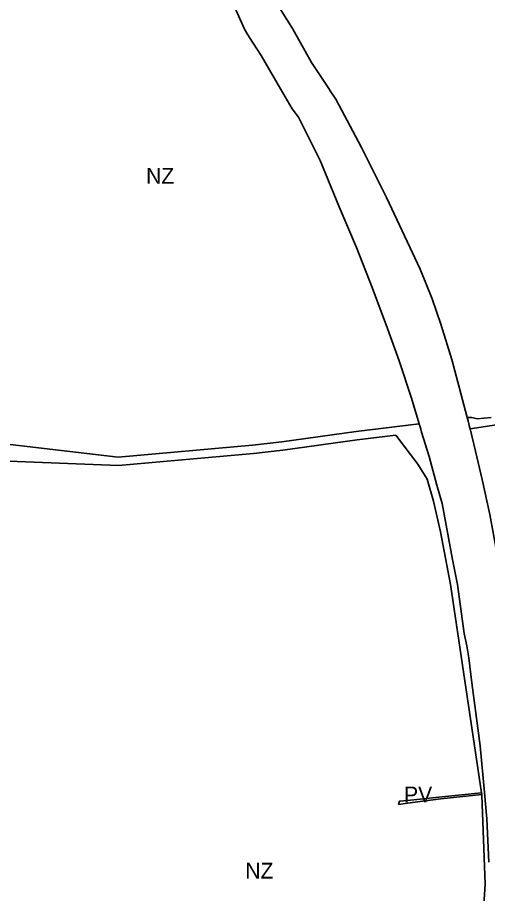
# Model space of a CAD drawing. Extents: x -650451 to -642268, y -1075216 to -1066610.
# Drawn here: x -645447 to -644999, y -1070421 to -1069586 of the extents above; entities that cross this region are included whole.
import ezdxf

# ---------------------------------------------------------------- set-up
doc = ezdxf.new("R2010")
doc.units = 0
doc.header["$LTSCALE"] = 6
doc.layers.add('1', color=7, linetype='Continuous', lineweight=35)
doc.layers.add('2', color=7, linetype='Continuous')

msp = doc.modelspace()

# ---------------------------------------------------------------- linework, layer by layer
at = {"layer": '1'}
msp.add_line((-645004.791, -1070324.889), (-645004.523, -1070326.697), dxfattribs=at)
for points in [[(-645064.052, -1069973.429), (-645071.53, -1069948.89), (-645083.31, -1069913.37), (-645094.42, -1069882.65), (-645108.74, -1069843.58), (-645123.84, -1069805.38), (-645140.27, -1069766.68), (-645153.44, -1069734.71), (-645158.43, -1069722.61), (-645179.12, -1069681.3), (-645185.17, -1069673.38), (-645198.41, -1069650.49), (-645214.76, -1069622.37), (-645225.7, -1069605.32), (-645227.27, -1069602.68), (-645230.42, -1069597.39), (-645242.75, -1069570.26)], [(-645018.28, -1069967.49), (-645024.45, -1069944.43), (-645032.85, -1069912.07), (-645043.5, -1069878.37), (-645051.78, -1069854.2), (-645063.26, -1069825.99), (-645095.1, -1069757.62), (-645118.98, -1069710.08), (-645143.56, -1069664.05), (-645148.8, -1069656.1), (-645150.3, -1069653.84), (-645153.33, -1069649.24), (-645166.67, -1069629), (-645184.88, -1069596.58), (-645202.56, -1069568.23)], [(-645015.548, -1069978.177), (-644917.567, -1069963.241), (-644816.43, -1069950.42), (-644811, -1069949.18), (-644786.59, -1069943.63), (-644697.64, -1069923.45), (-644570.98, -1069888.81), (-644560.98, -1069886.08), (-644475.46, -1069858.08), (-644434.96, -1069844.81), (-644431.06, -1069844.36), (-644427.69, -1069845.25), (-644424.29, -1069847.81), (-644422.37, -1069851.25), (-644408.42, -1069918.4), (-644394, -1069988.35), (-644378.24, -1070065.11), (-644378.11, -1070068.59), (-644379.29, -1070072.11), (-644382.02, -1070075.23), (-644385.73, -1070076.96), (-644423.99, -1070086.17)], [(-645469.701, -1069990.011), (-645453.852, -1069992.968), (-645350.784, -1070005.227), (-645222.809, -1069993.701), (-645195.011, -1069990.48), (-645124.233, -1069980.695), (-645064.052, -1069973.429)], [(-644997.87, -1070391.16), (-644999.47, -1070349.63), (-645001.81, -1070324.58), (-645005.98, -1070280.14), (-645013.77, -1070220.04), (-645016.92, -1070196.32), (-645018.56, -1070184.92), (-645021.14, -1070173.07), (-645027.49, -1070126.56), (-645032.21, -1070102.73), (-645042.27, -1070049.23), (-645047.28, -1070031.83), (-645054.73, -1070004.56), (-645061.76, -1069981.21), (-645062.57, -1069978.46), (-645063.23, -1069976.2), (-645063.96, -1069973.73), (-645064.052, -1069973.429)], [(-645018.28, -1069967.49), (-645013.9, -1069967.4), (-645008.74, -1069968.61), (-644995.54, -1069967.3)], [(-645015.548, -1069978.177), (-645016.01, -1069976.23), (-645017.46, -1069970.61), (-645018.28, -1069967.49)], [(-645015.548, -1069978.177), (-645010.54, -1069999.3), (-645004.02, -1070026.44), (-644996.88, -1070059.73), (-644989.62, -1070097.79), (-644984.21, -1070132.81), (-644979.57, -1070167.9), (-644978.49, -1070180.05), (-644976.94, -1070191.41), (-644974.49, -1070210.98), (-644974.29, -1070213.17), (-644974, -1070216.2), (-644971.47, -1070250.14), (-644970.36, -1070275.49), (-644970.55, -1070321.56)], [(-645004.791, -1070324.889), (-645034.122, -1070126.616), (-645043.92, -1070076.344), (-645050.293, -1070047.035), (-645056.555, -1070026.163), (-645065.235, -1070011.695), (-645086.484, -1069984.195), (-645123.206, -1069988.629), (-645194.003, -1069998.417), (-645221.99, -1070001.66), (-645350.591, -1070013.242), (-645455.073, -1070009.111), (-645454.881, -1070137.836), (-645466.862, -1070133.219), (-645499.142, -1070133.293)], [(-645004.791, -1070324.889), (-645045.31, -1070329.09), (-645075.22, -1070332.26), (-645082.85, -1070332.97), (-645083.74, -1070336.18), (-645075.2, -1070334.84), (-645043.33, -1070330.7), (-645004.523, -1070326.697)], [(-645004.523, -1070326.697), (-645004.434, -1070327.302), (-645001.312, -1070412.099), (-645004.327, -1070461.264), (-645014.277, -1070543.11), (-645023.048, -1070595.033), (-645039.574, -1070675.065), (-645045.493, -1070696.321), (-645059.308, -1070747.712), (-645059.403, -1070749.195)]]:
    msp.add_lwpolyline(points, dxfattribs=at)

# ---------------------------------------------------------------- texts
at = {"layer": '2'}
for s, p in [('NZ', (-645324.315, -1069744.623)), ('PV', (-645078.468, -1070334.109)), ('NZ', (-645229.737, -1070406.663))]:
    msp.add_text(s, height=15, dxfattribs=at).set_placement(p)

doc.saveas('drawing.dxf')
